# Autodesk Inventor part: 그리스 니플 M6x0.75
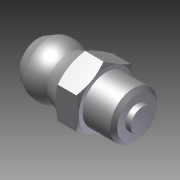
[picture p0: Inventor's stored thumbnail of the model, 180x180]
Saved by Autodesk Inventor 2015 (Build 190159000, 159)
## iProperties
Created: 2024-12
Part Number: 그리스 니플 M6x0.75
Material: 일반
Document SubType Name: Modeling
Designer: 10401
Density: 1 g/cm^3
Appearance: 기본값
Author: 10401
Author: jhkim
Description: 윤활 니플, 원추 유형 A
Creation Date: 2024-11-28
Sending System: Autodesk Inventor 2025
Preprocessor: ST-DEVELOPER v20
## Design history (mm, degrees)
node "그리스 니플 M6x0.751"
body "Solid1"
node "기준1"
